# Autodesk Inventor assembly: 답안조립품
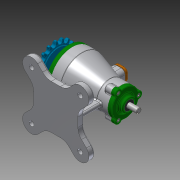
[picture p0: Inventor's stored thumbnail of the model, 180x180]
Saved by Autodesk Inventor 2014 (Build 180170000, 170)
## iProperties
Created: 2018-03
Part Number: 답안조립품
Document SubType Name: Assembly
Designer: kb542
Author: kb542
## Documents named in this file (15)
- C:\Users\kb542\Desktop\480307V1022\답안조립품.iam
- C:\Users\kb542\Desktop\480307V1022\본체1.ipt
- C:\Users\kb542\Desktop\480307V1022\뒤커버.ipt
- C:\Users\kb542\Desktop\480307V1022\마개.ipt
- C:\Users\kb542\Desktop\480307V1022\베어링-6200.ipt
- C:\Users\kb542\Desktop\480307V1022\베어링-6203.ipt
- C:\Users\kb542\Desktop\480307V1022\볼트 M4 x 12.ipt
- 볼트 M4 x 12.ipt
- C:\Users\kb542\Desktop\480307V1022\스프로킷.ipt
- C:\Users\kb542\Desktop\480307V1022\앞커버.ipt
- C:\Users\kb542\Desktop\480307V1022\오일 실 10 20 7.ipt
- C:\Users\kb542\Desktop\480307V1022\오일 실 17 30 8.ipt
- C:\Users\kb542\Desktop\480307V1022\축.ipt
- C:\Users\kb542\Desktop\480307V1022\키 5 x 5.ipt
- 키 5 x 5.ipt
## Component patterns: 구성요소 패턴 2:2 (6 elements), 구성요소 패턴 2:3 (6 elements), 구성요소 패턴 2:4 (6 elements), 구성요소 패턴 2:5 (6 elements), 구성요소 패턴 2:6 (6 elements)
